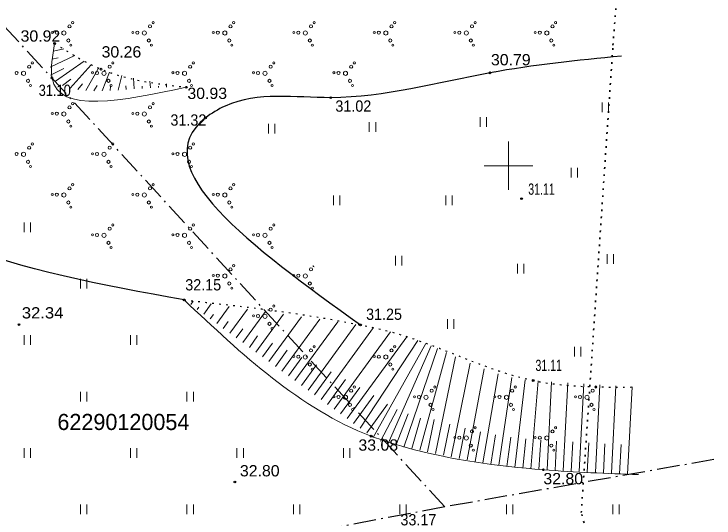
# Model space of a CAD drawing. Extents: x 380758 to 381729, y 283236 to 283533.
# Drawn here: x 381619.35 to 381662.74, y 283378.15 to 283409.41 of the extents above; entities that cross this region are included whole.
import ezdxf

# ---------------------------------------------------------------- set-up
doc = ezdxf.new("R2010")
doc.units = 0
doc.header["$LTSCALE"] = 0.28
doc.linetypes.add('DOT_DASHED', pattern=[7.7, 5, -1.2, 0.3, -1.2])
doc.linetypes.add('DOTTED', pattern=[1.5, 0.3, -1.2])
for name, color, linetype, lineweight in [('21', 7, 'Continuous', 25), ('23', 7, 'Continuous', 13), ('25', 7, 'DOTTED', 35), ('29', 7, 'DOT_DASHED', 25), ('30', 7, 'Continuous', 13), ('31', 7, 'Continuous', 13), ('58', 7, 'Continuous', 25)]:
    doc.layers.add(name, color=color, linetype=linetype, lineweight=lineweight)
doc.layers.add('59', color=7, linetype='Continuous')

msp = doc.modelspace()

# ---------------------------------------------------------------- linework, layer by layer
at = {"layer": '21'}
for points in [[(381629.894, 283391.678), (381609.358, 283403.077), (381609.389, 283404.028), (381612.077, 283416.846), (381609.55, 283427.454), (381609.24, 283436.712), (381609.657, 283437.761), (381619.239, 283434.927)], [(381657.003, 283406.797), (381648.856, 283405.761), (381638.98, 283404.22), (381632.444, 283403.701), (381631.219, 283402.968), (381640.827, 283390.129)]]:
    msp.add_spline(points, degree=3, dxfattribs=at)
at = {"layer": '23'}
for p, q in [((381655.804, 283403.312), (381655.804, 283403.912)), ((381656.204, 283403.312), (381656.204, 283403.912)), ((381648.235, 283402.403), (381648.235, 283403.003)), ((381648.635, 283402.403), (381648.635, 283403.003)), ((381635.113, 283401.999), (381635.113, 283402.599)), ((381635.513, 283401.999), (381635.513, 283402.599)), ((381641.371, 283402.1), (381641.371, 283402.7)), ((381641.771, 283402.1), (381641.771, 283402.7)), ((381653.887, 283399.271), (381653.887, 283399.871)), ((381654.287, 283399.271), (381654.287, 283399.871)), ((381639.151, 283397.554), (381639.151, 283398.154)), ((381639.551, 283397.554), (381639.551, 283398.154)), ((381646.115, 283397.554), (381646.115, 283398.154)), ((381646.515, 283397.554), (381646.515, 283398.154)), ((381619.967, 283395.882), (381619.967, 283396.482)), ((381620.367, 283395.882), (381620.367, 283396.482)), ((381642.986, 283393.817), (381642.986, 283394.417)), ((381643.386, 283393.817), (381643.386, 283394.417)), ((381656.107, 283393.918), (381656.107, 283394.518)), ((381656.507, 283393.918), (381656.507, 283394.518)), ((381650.556, 283393.312), (381650.556, 283393.912)), ((381650.956, 283393.312), (381650.956, 283393.912)), ((381623.467, 283392.382), (381623.467, 283392.982)), ((381623.867, 283392.382), (381623.867, 283392.982)), ((381646.216, 283389.878), (381646.216, 283390.478)), ((381646.616, 283389.878), (381646.616, 283390.478)), ((381619.967, 283388.882), (381619.967, 283389.482)), ((381620.367, 283388.882), (381620.367, 283389.482)), ((381626.567, 283388.882), (381626.567, 283389.482)), ((381626.967, 283388.882), (381626.967, 283389.482)), ((381654.089, 283388.161), (381654.089, 283388.761)), ((381654.489, 283388.161), (381654.489, 283388.761)), ((381623.467, 283385.382), (381623.467, 283385.982)), ((381623.867, 283385.382), (381623.867, 283385.982)), ((381630.067, 283385.382), (381630.067, 283385.982)), ((381630.467, 283385.382), (381630.467, 283385.982)), ((381619.967, 283381.882), (381619.967, 283382.482)), ((381620.367, 283381.882), (381620.367, 283382.482)), ((381626.567, 283381.882), (381626.567, 283382.482)), ((381626.967, 283381.882), (381626.967, 283382.482)), ((381633.167, 283381.882), (381633.167, 283382.482)), ((381633.567, 283381.882), (381633.567, 283382.482)), ((381639.767, 283381.882), (381639.767, 283382.482)), ((381640.167, 283381.882), (381640.167, 283382.482)), ((381623.467, 283378.382), (381623.467, 283378.982)), ((381623.867, 283378.382), (381623.867, 283378.982)), ((381630.067, 283378.382), (381630.067, 283378.982)), ((381630.467, 283378.382), (381630.467, 283378.982)), ((381636.667, 283378.382), (381636.667, 283378.982)), ((381637.067, 283378.382), (381637.067, 283378.982)), ((381643.267, 283378.382), (381643.267, 283378.982)), ((381643.667, 283378.382), (381643.667, 283378.982)), ((381649.867, 283378.382), (381649.867, 283378.982)), ((381650.267, 283378.382), (381650.267, 283378.982)), ((381656.467, 283378.382), (381656.467, 283378.982)), ((381656.867, 283378.382), (381656.867, 283378.982))]:
    msp.add_line(p, q, dxfattribs=at)
for centre, radius in [((381622.9822, 283408.8721), 0.064), ((381627.9722, 283408.8721), 0.064), ((381632.9622, 283408.8721), 0.064), ((381637.9522, 283408.8721), 0.064), ((381642.9422, 283408.8721), 0.064), ((381647.9322, 283408.8721), 0.064), ((381652.9222, 283408.8721), 0.064), ((381622.7857, 283408.6404), 0.096), ((381627.7757, 283408.6404), 0.096), ((381632.7657, 283408.6404), 0.096), ((381637.7557, 283408.6404), 0.096), ((381642.7457, 283408.6404), 0.096), ((381647.7357, 283408.6404), 0.096), ((381652.7257, 283408.6404), 0.096), ((381621.7198, 283408.2669), 0.064), ((381622.0043, 283408.2535), 0.096), ((381622.4382, 283408.2327), 0.128), ((381626.7098, 283408.2669), 0.064), ((381626.9943, 283408.2535), 0.096), ((381627.4282, 283408.2327), 0.128), ((381631.6998, 283408.2669), 0.064), ((381631.9843, 283408.2535), 0.096), ((381632.4182, 283408.2327), 0.128), ((381636.6898, 283408.2669), 0.064), ((381636.9743, 283408.2535), 0.096), ((381637.4082, 283408.2327), 0.128), ((381641.6798, 283408.2669), 0.064), ((381641.9643, 283408.2535), 0.096), ((381642.3982, 283408.2327), 0.128), ((381646.6698, 283408.2669), 0.064), ((381646.9543, 283408.2535), 0.096), ((381647.3882, 283408.2327), 0.128), ((381651.6598, 283408.2669), 0.064), ((381651.9443, 283408.2535), 0.096), ((381652.3782, 283408.2327), 0.128), ((381622.7147, 283407.7658), 0.096), ((381627.7047, 283407.7658), 0.096), ((381632.6947, 283407.7658), 0.096), ((381637.6847, 283407.7658), 0.096), ((381642.6747, 283407.7658), 0.096), ((381647.6647, 283407.7658), 0.096), ((381652.6547, 283407.7658), 0.096), ((381622.8721, 283407.4765), 0.064), ((381627.8621, 283407.4765), 0.064), ((381632.8521, 283407.4765), 0.064), ((381637.8421, 283407.4765), 0.064), ((381642.8321, 283407.4765), 0.064), ((381647.8221, 283407.4765), 0.064), ((381652.8121, 283407.4765), 0.064), ((381620.4822, 283406.3721), 0.064), ((381625.4722, 283406.3721), 0.064), ((381630.4622, 283406.3721), 0.064), ((381635.4522, 283406.3721), 0.064), ((381640.4422, 283406.3721), 0.064), ((381620.2857, 283406.1404), 0.096), ((381625.2757, 283406.1404), 0.096), ((381630.2657, 283406.1404), 0.096), ((381635.2557, 283406.1404), 0.096), ((381640.2457, 283406.1404), 0.096), ((381619.5043, 283405.7535), 0.096), ((381619.9382, 283405.7327), 0.128), ((381624.2098, 283405.7669), 0.064), ((381624.4943, 283405.7535), 0.096), ((381624.9282, 283405.7327), 0.128), ((381629.1998, 283405.7669), 0.064), ((381629.4843, 283405.7535), 0.096), ((381629.9182, 283405.7327), 0.128), ((381634.1898, 283405.7669), 0.064), ((381634.4743, 283405.7535), 0.096), ((381634.9082, 283405.7327), 0.128), ((381639.1798, 283405.7669), 0.064), ((381639.4643, 283405.7535), 0.096), ((381639.8982, 283405.7327), 0.128), ((381620.2147, 283405.2658), 0.096), ((381620.3721, 283404.9765), 0.064), ((381625.2047, 283405.2658), 0.096), ((381625.3621, 283404.9765), 0.064), ((381630.1947, 283405.2658), 0.096), ((381630.3521, 283404.9765), 0.064), ((381635.1847, 283405.2658), 0.096), ((381635.3421, 283404.9765), 0.064), ((381640.1747, 283405.2658), 0.096), ((381640.3321, 283404.9765), 0.064), ((381622.9822, 283403.8481), 0.064), ((381627.9722, 283403.8481), 0.064), ((381621.7198, 283403.2429), 0.064), ((381622.0043, 283403.2295), 0.096), ((381622.4382, 283403.2087), 0.128), ((381622.7857, 283403.6164), 0.096), ((381626.7098, 283403.2429), 0.064), ((381626.9943, 283403.2295), 0.096), ((381627.4282, 283403.2087), 0.128), ((381627.7757, 283403.6164), 0.096), ((381622.7147, 283402.7418), 0.096), ((381622.8721, 283402.4525), 0.064), ((381627.7047, 283402.7418), 0.096), ((381627.8621, 283402.4525), 0.064), ((381620.2857, 283401.1164), 0.096), ((381620.4822, 283401.3481), 0.064), ((381625.2757, 283401.1164), 0.096), ((381625.4722, 283401.3481), 0.064), ((381630.2657, 283401.1164), 0.096), ((381630.4622, 283401.3481), 0.064), ((381619.5043, 283400.7295), 0.096), ((381619.9382, 283400.7087), 0.128), ((381624.2098, 283400.7429), 0.064), ((381624.4943, 283400.7295), 0.096), ((381624.9282, 283400.7087), 0.128), ((381629.1998, 283400.7429), 0.064), ((381629.4843, 283400.7295), 0.096), ((381629.9182, 283400.7087), 0.128), ((381620.2147, 283400.2418), 0.096), ((381625.2047, 283400.2418), 0.096), ((381630.1947, 283400.2418), 0.096), ((381620.3721, 283399.9525), 0.064), ((381625.3621, 283399.9525), 0.064), ((381630.3521, 283399.9525), 0.064), ((381622.7857, 283398.5924), 0.096), ((381622.9822, 283398.8241), 0.064), ((381627.7757, 283398.5924), 0.096), ((381627.9722, 283398.8241), 0.064), ((381632.7657, 283398.5924), 0.096), ((381632.9622, 283398.8241), 0.064), ((381621.7198, 283398.2189), 0.064), ((381622.0043, 283398.2055), 0.096), ((381622.4382, 283398.1847), 0.128), ((381626.7098, 283398.2189), 0.064), ((381626.9943, 283398.2055), 0.096), ((381627.4282, 283398.1847), 0.128), ((381631.6998, 283398.2189), 0.064), ((381631.9843, 283398.2055), 0.096), ((381632.4182, 283398.1847), 0.128), ((381622.7147, 283397.7178), 0.096), ((381627.7047, 283397.7178), 0.096), ((381632.6947, 283397.7178), 0.096), ((381622.8721, 283397.4285), 0.064), ((381627.8621, 283397.4285), 0.064), ((381632.8521, 283397.4285), 0.064), ((381625.4722, 283396.3241), 0.064), ((381630.4622, 283396.3241), 0.064), ((381635.4522, 283396.3241), 0.064), ((381625.2757, 283396.0924), 0.096), ((381630.2657, 283396.0924), 0.096), ((381635.2557, 283396.0924), 0.096), ((381624.2098, 283395.7189), 0.064), ((381624.4943, 283395.7055), 0.096), ((381624.9282, 283395.6847), 0.128), ((381629.1998, 283395.7189), 0.064), ((381629.4843, 283395.7055), 0.096), ((381629.9182, 283395.6847), 0.128), ((381634.1898, 283395.7189), 0.064), ((381634.4743, 283395.7055), 0.096), ((381634.9082, 283395.6847), 0.128), ((381625.2047, 283395.2178), 0.096), ((381630.1947, 283395.2178), 0.096), ((381635.1847, 283395.2178), 0.096), ((381625.3621, 283394.9285), 0.064), ((381630.3521, 283394.9285), 0.064), ((381635.3421, 283394.9285), 0.064), ((381632.9622, 283393.8001), 0.064), ((381632.7657, 283393.5684), 0.096), ((381637.7557, 283393.5684), 0.096), ((381631.6998, 283393.1949), 0.064), ((381631.9843, 283393.1815), 0.096), ((381632.4182, 283393.1607), 0.128), ((381636.6898, 283393.1949), 0.064), ((381636.9743, 283393.1815), 0.096), ((381637.4082, 283393.1607), 0.128), ((381632.6947, 283392.6938), 0.096), ((381632.8521, 283392.4045), 0.064), ((381637.6847, 283392.6938), 0.096), ((381637.8421, 283392.4045), 0.064), ((381635.2557, 283391.0684), 0.096), ((381635.4522, 283391.3001), 0.064), ((381634.1898, 283390.6949), 0.064), ((381634.4743, 283390.6815), 0.096), ((381634.9082, 283390.6607), 0.128), ((381635.1847, 283390.1938), 0.096), ((381635.3421, 283389.9045), 0.064), ((381637.7557, 283388.5444), 0.096), ((381637.9522, 283388.7761), 0.064), ((381642.7457, 283388.5444), 0.096), ((381642.9422, 283388.7761), 0.064), ((381636.6898, 283388.1709), 0.064), ((381636.9743, 283388.1575), 0.096), ((381637.4082, 283388.1367), 0.128), ((381641.6798, 283388.1709), 0.064), ((381641.9643, 283388.1575), 0.096), ((381642.3982, 283388.1367), 0.128), ((381637.6847, 283387.6698), 0.096), ((381642.6747, 283387.6698), 0.096), ((381637.8421, 283387.3805), 0.064), ((381642.8321, 283387.3805), 0.064), ((381640.2457, 283386.0444), 0.096), ((381640.4422, 283386.2761), 0.064), ((381645.2357, 283386.0444), 0.096), ((381645.4322, 283386.2761), 0.064), ((381650.2257, 283386.0444), 0.096), ((381650.4222, 283386.2761), 0.064), ((381655.2157, 283386.0444), 0.096), ((381655.4122, 283386.2761), 0.064), ((381639.1798, 283385.6709), 0.064), ((381639.4643, 283385.6575), 0.096), ((381639.8982, 283385.6367), 0.128), ((381644.1698, 283385.6709), 0.064), ((381644.4543, 283385.6575), 0.096), ((381644.8882, 283385.6367), 0.128), ((381649.1598, 283385.6709), 0.064), ((381649.4443, 283385.6575), 0.096), ((381649.8782, 283385.6367), 0.128), ((381654.1498, 283385.6709), 0.064), ((381654.4343, 283385.6575), 0.096), ((381654.8682, 283385.6367), 0.128), ((381640.1747, 283385.1698), 0.096), ((381645.1647, 283385.1698), 0.096), ((381650.1547, 283385.1698), 0.096), ((381655.1447, 283385.1698), 0.096), ((381640.3321, 283384.8805), 0.064), ((381645.3221, 283384.8805), 0.064), ((381650.3121, 283384.8805), 0.064), ((381655.3021, 283384.8805), 0.064), ((381647.9322, 283383.7521), 0.064), ((381652.9222, 283383.7521), 0.064), ((381647.7357, 283383.5204), 0.096), ((381652.7257, 283383.5204), 0.096), ((381646.6698, 283383.1469), 0.064), ((381646.9543, 283383.1335), 0.096), ((381647.3882, 283383.1127), 0.128), ((381651.6598, 283383.1469), 0.064), ((381651.9443, 283383.1335), 0.096), ((381652.3782, 283383.1127), 0.128), ((381647.6647, 283382.6458), 0.096), ((381652.6547, 283382.6458), 0.096), ((381647.8221, 283382.3565), 0.064), ((381652.8121, 283382.3565), 0.064)]:
    msp.add_circle(centre, radius, dxfattribs=at)
for centre, start, end in [((381649.1598, 283405.7669), 37.29977, 155.49814), ((381637.9522, 283393.8001), 165.71218, 266.30343)]:
    msp.add_arc(centre, 0.064, start, end, dxfattribs=at)
at = {"layer": '25'}
msp.add_lwpolyline([(381572.085, 283346.757), (381611.455, 283348.662), (381649.963, 283356.155), (381659.737, 283359.354), (381654.512, 283378.485), (381656.478, 283407.485), (381656.785, 283411.384)], dxfattribs=at)
at = {"layer": '29'}
for p, q in [((381662.74, 283381.778), (381646.05, 283378.842)), ((381646.05, 283378.842), (381617.917, 283373.524))]:
    msp.add_line(p, q, dxfattribs=at)
msp.add_lwpolyline([(381646.05, 283378.842), (381606.798, 283421.7), (381591.309, 283451.227), (381583.305, 283465.736)], dxfattribs=at)
at = {"layer": '30'}
for points in [[(381650, 283401.5), (381650, 283400), (381650, 283398.5)], [(381648.5, 283400), (381650, 283400), (381651.5, 283400)]]:
    msp.add_lwpolyline(points, dxfattribs=at)
at = {"layer": '31'}
for p, q in [((381621.786, 283407.097), (381622.432, 283407.255)), ((381621.596, 283406.115), (381623.111, 283406.834)), ((381621.682, 283406.608), (381622.08, 283406.694)), ((381621.916, 283405.234), (381623.706, 283406.481)), ((381621.611, 283405.619), (381622.431, 283406.024)), ((381622.818, 283404.819), (381624.129, 283406.255)), ((381623.805, 283404.671), (381624.584, 283406.048)), ((381624.805, 283404.65), (381625.272, 283405.805)), ((381625.804, 283404.691), (381626.024, 283405.598)), ((381622.345, 283404.98), (381622.874, 283405.366)), ((381623.308, 283404.723), (381623.599, 283405.071)), ((381626.802, 283404.759), (381626.752, 283405.432)), ((381627.799, 283404.83), (381627.772, 283405.25)), ((381628.798, 283404.88), (381628.792, 283405.083)), ((381624.305, 283404.65), (381624.495, 283404.981)), ((381625.305, 283404.665), (381625.323, 283404.912)), ((381626.303, 283404.723), (381626.287, 283404.947)), ((381627.3, 283404.795), (381627.29, 283404.935)), ((381628.298, 283404.859), (381628.295, 283404.927)), ((381630.298, 283391.384), (381630.455, 283391.599)), ((381630.702, 283391.089), (381630.801, 283391.224)), ((381631.106, 283390.795), (381631.57, 283391.432)), ((381631.914, 283390.206), (381632.692, 283391.273)), ((381631.51, 283390.5), (381631.713, 283390.779)), ((381632.723, 283389.617), (381633.813, 283391.114)), ((381633.531, 283389.028), (381634.935, 283390.955)), ((381634.339, 283388.439), (381636.056, 283390.796)), ((381632.319, 283389.911), (381632.626, 283390.333)), ((381635.147, 283387.85), (381637.178, 283390.637)), ((381635.955, 283387.261), (381638.3, 283390.478)), ((381636.764, 283386.672), (381639.421, 283390.319)), ((381633.127, 283389.322), (381633.539, 283389.888)), ((381637.572, 283386.083), (381640.543, 283390.16)), ((381638.38, 283385.495), (381641.637, 283389.964)), ((381633.935, 283388.733), (381634.451, 283389.442)), ((381639.188, 283384.906), (381642.676, 283389.692)), ((381639.996, 283384.317), (381643.699, 283389.398)), ((381634.743, 283388.145), (381635.364, 283388.997)), ((381640.805, 283383.728), (381644.371, 283389.171)), ((381641.616, 283383.143), (381644.871, 283388.975)), ((381635.551, 283387.556), (381636.277, 283388.551)), ((381642.537, 283382.764), (381645.206, 283388.824)), ((381643.515, 283382.555), (381645.596, 283388.667)), ((381636.36, 283386.967), (381637.189, 283388.105)), ((381644.494, 283382.353), (381646.161, 283388.415)), ((381645.473, 283382.149), (381646.719, 283388.153)), ((381646.453, 283381.949), (381647.618, 283387.756)), ((381637.168, 283386.378), (381638.102, 283387.66)), ((381647.434, 283381.757), (381648.496, 283387.399)), ((381637.976, 283385.789), (381639.01, 283387.208)), ((381648.419, 283381.581), (381649.356, 283387.098)), ((381649.406, 283381.424), (381650.201, 283386.868)), ((381638.784, 283385.2), (381639.904, 283386.737)), ((381650.398, 283381.293), (381651.03, 283386.719)), ((381651.393, 283381.194), (381651.839, 283386.652)), ((381652.391, 283381.131), (381652.671, 283386.6)), ((381653.389, 283381.08), (381653.669, 283386.538)), ((381654.388, 283381.029), (381654.667, 283386.475)), ((381655.387, 283380.978), (381655.665, 283386.413)), ((381639.592, 283384.611), (381640.787, 283386.25)), ((381656.385, 283380.927), (381656.663, 283386.351)), ((381657.384, 283380.876), (381657.661, 283386.288)), ((381640.401, 283384.022), (381641.659, 283385.75)), ((381641.209, 283383.433), (381642.51, 283385.219)), ((381642.062, 283382.918), (381643.108, 283384.883)), ((381643.024, 283382.651), (381643.784, 283384.619)), ((381644.005, 283382.455), (381644.554, 283384.337)), ((381644.984, 283382.251), (381645.401, 283384.252)), ((381645.963, 283382.048), (381646.359, 283383.982)), ((381646.943, 283381.851), (381647.31, 283383.73)), ((381647.926, 283381.667), (381648.256, 283383.503)), ((381648.912, 283381.499), (381649.199, 283383.311)), ((381649.901, 283381.355), (381650.14, 283383.16)), ((381650.895, 283381.24), (381651.076, 283383.056)), ((381651.891, 283381.158), (381652.005, 283382.98)), ((381652.89, 283381.106), (381652.983, 283382.925)), ((381653.889, 283381.055), (381653.982, 283382.87)), ((381654.887, 283381.004), (381654.98, 283382.815)), ((381655.886, 283380.952), (381655.979, 283382.76)), ((381656.885, 283380.901), (381656.977, 283382.706))]:
    msp.add_line(p, q, dxfattribs=at)
for points in [[(381621.86, 283407.591), (381621.705, 283405.434), (381630.026, 283404.865)], [(381629.894, 283391.678), (381641.492, 283383.227), (381643.654, 283382.527), (381652.163, 283381.143), (381658.058, 283380.841)]]:
    msp.add_spline(points, degree=3, dxfattribs=at)
at = {"layer": '31', "linetype": 'DOTTED', "lineweight": 25}
for points in [[(381621.86, 283407.591), (381624.742, 283405.986), (381630.026, 283404.865)], [(381629.894, 283391.678), (381640.827, 283390.129), (381643.056, 283389.598), (381651.535, 283386.681), (381657.949, 283386.28)]]:
    msp.add_spline(points, degree=3, dxfattribs=at)
at = {"layer": '58'}
for centre in [(381621.86, 283407.5911), (381624.742, 283405.9861), (381621.705, 283405.4341), (381648.856, 283405.7611), (381630.026, 283404.8651), (381638.98, 283404.2201), (381631.219, 283402.9681), (381650.812, 283397.9591), (381629.894, 283391.6781), (381619.659, 283390.1481), (381640.827, 283390.1291), (381651.535, 283386.6811), (381641.492, 283383.2271), (381652.163, 283381.1431), (381633.041, 283380.3881)]:
    msp.add_circle(centre, 0.0534, dxfattribs=at)

# ---------------------------------------------------------------- texts
for s, width, p in [('30.92', 1.05, (381619.754, 283407.694)), ('30.26', 1.05, (381624.776, 283406.711)), ('30.79', 1.05, (381648.913, 283406.224)), ('31.10', 0.85, (381620.876, 283404.328)), ('30.93', 1.05, (381630.095, 283404.139)), ('31.02', 0.95, (381639.269, 283403.35)), ('31.32', 0.95, (381629.044, 283402.484)), ('31.11', 0.7, (381651.226, 283398.2)), ('32.15', 0.95, (381629.963, 283392.265)), ('32.34', 1.1, (381619.831, 283390.527)), ('31.25', 0.95, (381641.172, 283390.439)), ('31.11', 0.7, (381651.673, 283387.268)), ('33.08', 1.05, (381640.698, 283382.328)), ('32.80', 1.05, (381633.351, 283380.733)), ('32.80', 1.05, (381652.163, 283380.244)), ('33.17', 0.95, (381643.304, 283377.695))]:
    msp.add_text(s, height=0.7, dxfattribs=dict(at, width=width)).set_placement(p)
at = {"layer": '59'}
msp.add_text('62290120054', height=1, dxfattribs=at).set_placement((381622.037, 283383.609))

doc.saveas('drawing.dxf')
